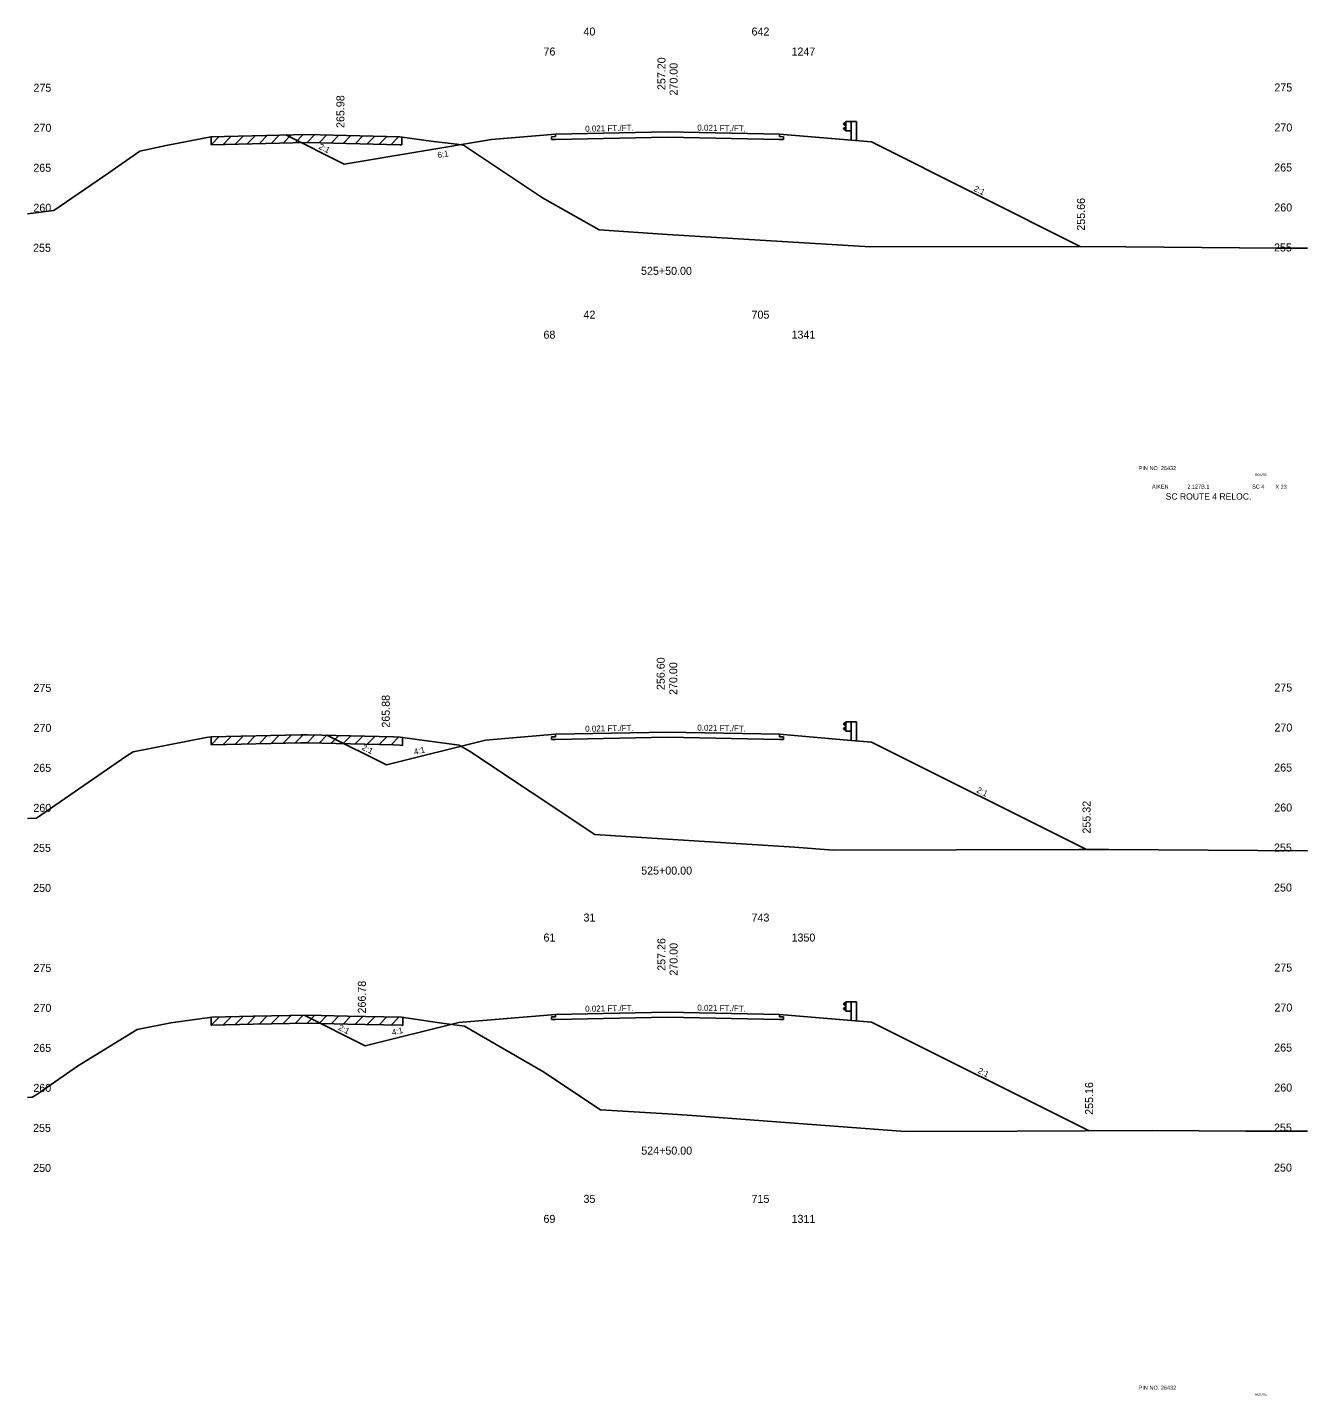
# Model space of a CAD drawing. Extents: x 2967 to 4323, y -3677 to -817.
# Drawn here: x 3188.8 to 3348.8, y -1162.8 to -991.8 of the extents above; entities that cross this region are included whole.
import ezdxf

# ---------------------------------------------------------------- set-up
doc = ezdxf.new("R2010")
doc.units = 0
for name, color, linetype in [('Level 1', 7, 'Continuous'), ('Level 10', 7, 'Continuous'), ('Level 11', 7, 'Continuous'), ('Level 12', 7, 'Continuous'), ('Level 20', 7, 'Continuous'), ('Level 24', 7, 'Continuous'), ('Level 3', 7, 'Continuous'), ('Level 32', 7, 'Continuous'), ('Level 33', 7, 'Continuous'), ('Level 59', 7, 'Continuous'), ('Level 6', 7, 'Continuous'), ('Level 60', 7, 'Continuous'), ('Level 61', 7, 'Continuous'), ('Level 7', 7, 'Continuous')]:
    doc.layers.add(name, color=color, linetype=linetype)

msp = doc.modelspace()

# ---------------------------------------------------------------- linework, layer by layer
at = {"layer": 'Level 11'}
for p, q in [((3254.76, -1005.43), (3254.26, -1005.44)), ((3254.26, -1005.44), (3254.26, -1005.78)), ((3254.76, -1005.13), (3254.76, -1005.43)), ((3282.76, -1005.43), (3282.76, -1005.13)), ((3283.26, -1005.44), (3282.76, -1005.43)), ((3283.26, -1005.78), (3283.26, -1005.44)), ((3254.26, -1005.78), (3254.76, -1005.77)), ((3282.76, -1005.77), (3283.26, -1005.78)), ((3254.76, -1080.43), (3254.26, -1080.44)), ((3254.26, -1080.44), (3254.26, -1080.78)), ((3254.26, -1080.78), (3254.76, -1080.77)), ((3254.76, -1080.13), (3254.76, -1080.43)), ((3282.76, -1080.43), (3282.76, -1080.13)), ((3283.26, -1080.44), (3282.76, -1080.43)), ((3282.76, -1080.77), (3283.26, -1080.78)), ((3283.26, -1080.78), (3283.26, -1080.44)), ((3254.76, -1115.43), (3254.26, -1115.44)), ((3254.26, -1115.44), (3254.26, -1115.78)), ((3254.26, -1115.78), (3254.76, -1115.77)), ((3254.76, -1115.13), (3254.76, -1115.43)), ((3282.76, -1115.43), (3282.76, -1115.13)), ((3283.26, -1115.44), (3282.76, -1115.43)), ((3282.76, -1115.77), (3283.26, -1115.78)), ((3283.26, -1115.78), (3283.26, -1115.44))]:
    msp.add_line(p, q, dxfattribs=at)
at = {"layer": 'Level 12'}
for p, q in [((3268.76, -1005.48), (3254.76, -1005.77)), ((3282.76, -1005.77), (3268.76, -1005.48)), ((3268.76, -1080.48), (3254.76, -1080.77)), ((3282.76, -1080.77), (3268.76, -1080.48)), ((3268.76, -1115.48), (3254.76, -1115.77)), ((3282.76, -1115.77), (3268.76, -1115.48))]:
    msp.add_line(p, q, dxfattribs=at)
at = {"layer": 'Level 24'}
for p, q in [((3291.03, -1003.62), (3290.76, -1003.82)), ((3290.76, -1003.82), (3290.76, -1003.87)), ((3291.03, -1004.72), (3291.03, -1003.55)), ((3291.03, -1003.55), (3291.7, -1003.55)), ((3291.7, -1003.55), (3291.7, -1005.88)), ((3291.7, -1003.55), (3292.36, -1003.55)), ((3292.36, -1003.55), (3292.36, -1005.93)), ((3290.76, -1003.87), (3291.03, -1004.07)), ((3290.76, -1004.39), (3291.03, -1004.19)), ((3290.76, -1004.44), (3290.76, -1004.39)), ((3291.03, -1004.64), (3290.76, -1004.44)), ((3291.03, -1004.72), (3291.7, -1004.72)), ((3291.03, -1078.62), (3290.76, -1078.82)), ((3290.76, -1078.82), (3290.76, -1078.87)), ((3290.76, -1078.87), (3291.03, -1079.07)), ((3291.03, -1079.72), (3291.03, -1078.55)), ((3291.03, -1078.55), (3291.7, -1078.55)), ((3291.7, -1078.55), (3291.7, -1080.88)), ((3291.7, -1078.55), (3292.36, -1078.55)), ((3292.36, -1078.55), (3292.36, -1080.93)), ((3290.76, -1079.39), (3291.03, -1079.19)), ((3290.76, -1079.44), (3290.76, -1079.39)), ((3291.03, -1079.64), (3290.76, -1079.44)), ((3291.03, -1079.72), (3291.7, -1079.72)), ((3291.03, -1113.62), (3290.76, -1113.82)), ((3290.76, -1113.82), (3290.76, -1113.87)), ((3290.76, -1113.87), (3291.03, -1114.07)), ((3290.76, -1114.39), (3291.03, -1114.19)), ((3290.76, -1114.44), (3290.76, -1114.39)), ((3291.03, -1114.64), (3290.76, -1114.44)), ((3291.03, -1114.72), (3291.03, -1113.55)), ((3291.03, -1113.55), (3291.7, -1113.55)), ((3291.03, -1114.72), (3291.7, -1114.72)), ((3291.7, -1113.55), (3291.7, -1115.88)), ((3291.7, -1113.55), (3292.36, -1113.55)), ((3292.36, -1113.55), (3292.36, -1115.93))]:
    msp.add_line(p, q, dxfattribs=at)
at = {"layer": 'Level 59'}
for p, q in [((3254.76, -1005.13), (3268.76, -1004.84)), ((3268.76, -1004.84), (3282.76, -1005.13)), ((3254.76, -1080.13), (3268.76, -1079.84)), ((3268.76, -1079.84), (3282.76, -1080.13)), ((3254.76, -1115.13), (3268.76, -1114.84)), ((3268.76, -1114.84), (3282.76, -1115.13))]:
    msp.add_line(p, q, dxfattribs=at)
at = {"layer": 'Level 6'}
for p, q in [((3246.76, -1005.8), (3254.76, -1005.13)), ((3282.76, -1005.13), (3290.76, -1005.8)), ((3290.76, -1005.8), (3294.26, -1006.09)), ((3246.01, -1080.86), (3254.76, -1080.13)), ((3282.76, -1080.13), (3290.76, -1080.8)), ((3290.76, -1080.8), (3294.26, -1081.09)), ((3246.01, -1080.86), (3233.62, -1083.96)), ((3242.68, -1116.14), (3230.99, -1119.06)), ((3242.68, -1116.14), (3254.76, -1115.13)), ((3282.76, -1115.13), (3290.76, -1115.8)), ((3290.76, -1115.8), (3294.26, -1116.09))]:
    msp.add_line(p, q, dxfattribs=at)
at = {"layer": 'Level 60'}
for p, q in [((3206.12, -1006.54), (3211.69, -1005.44)), ((3211.69, -1005.44), (3218.54, -1005.29)), ((3218.54, -1005.29), (3223.7, -1005.16)), ((3223.7, -1005.16), (3230.3, -1005.32)), ((3230.3, -1005.32), (3235.31, -1005.44)), ((3235.31, -1005.44), (3239.52, -1006.02)), ((3198.95, -1009.94), (3202.8, -1007.24)), ((3202.8, -1007.24), (3206.12, -1006.54)), ((3239.52, -1006.02), (3242.41, -1006.36)), ((3242.41, -1006.36), (3243.25, -1006.48)), ((3243.25, -1006.48), (3253.14, -1013.09)), ((3192.08, -1014.68), (3198.95, -1009.94)), ((3253.14, -1013.09), (3260.21, -1017.08)), ((3188.76, -1015.06), (3192.08, -1014.68)), ((3260.21, -1017.08), (3268.76, -1017.64)), ((3268.76, -1017.64), (3276.91, -1018.18)), ((3276.91, -1018.18), (3294.08, -1019.19)), ((3294.08, -1019.19), (3315.44, -1019.14)), ((3315.44, -1019.14), (3326.04, -1019.22)), ((3326.04, -1019.22), (3344.98, -1019.36)), ((3344.98, -1019.36), (3348.76, -1019.36)), ((3201.98, -1082.33), (3211.09, -1080.53)), ((3211.09, -1080.53), (3211.71, -1080.45)), ((3211.71, -1080.45), (3222.92, -1080.19)), ((3222.92, -1080.19), (3223.75, -1080.18)), ((3223.75, -1080.18), (3234.5, -1080.45)), ((3234.5, -1080.45), (3235.34, -1080.47)), ((3235.34, -1080.47), (3235.92, -1080.55)), ((3235.92, -1080.55), (3242.72, -1081.49)), ((3201.08, -1082.89), (3201.98, -1082.33)), ((3242.72, -1081.49), (3244.01, -1082.24)), ((3244.01, -1082.24), (3259.69, -1092.66)), ((3189.91, -1090.61), (3201.08, -1082.89)), ((3188.76, -1090.66), (3189.91, -1090.61)), ((3259.69, -1092.66), (3268.76, -1093.24)), ((3268.76, -1093.24), (3284.62, -1094.24)), ((3284.62, -1094.24), (3289.48, -1094.61)), ((3289.48, -1094.61), (3320.21, -1094.53)), ((3320.21, -1094.53), (3323.9, -1094.51)), ((3323.9, -1094.51), (3348.76, -1094.68)), ((3202.5, -1117.02), (3206.68, -1116.19)), ((3206.68, -1116.19), (3211.82, -1115.48)), ((3211.82, -1115.48), (3216.97, -1115.36)), ((3216.97, -1115.36), (3223.79, -1115.23)), ((3223.79, -1115.23), (3228.75, -1115.35)), ((3228.75, -1115.35), (3235.52, -1115.5)), ((3235.52, -1115.5), (3240.27, -1116.19)), ((3240.27, -1116.19), (3243.4, -1116.62)), ((3243.4, -1116.62), (3253.19, -1122.26)), ((3195.03, -1121.62), (3202.5, -1117.02)), ((3189.93, -1125.14), (3195.03, -1121.62)), ((3253.19, -1122.26), (3260.38, -1127.05)), ((3189.36, -1125.49), (3189.93, -1125.14)), ((3188.76, -1125.51), (3189.36, -1125.49)), ((3260.38, -1127.05), (3268.76, -1127.58)), ((3268.76, -1127.58), (3271.84, -1127.78)), ((3271.84, -1127.78), (3298.48, -1129.79)), ((3298.48, -1129.79), (3312.44, -1129.75)), ((3312.44, -1129.75), (3329.43, -1129.63)), ((3329.43, -1129.63), (3340.98, -1129.71)), ((3340.98, -1129.71), (3348.76, -1129.71))]:
    msp.add_line(p, q, dxfattribs=at)
at = {"layer": 'Level 61'}
for p, q in [((3212.74, -1005.42), (3211.72, -1006.44)), ((3211.72, -1005.44), (3211.72, -1006.44)), ((3214.24, -1005.38), (3213.22, -1006.41)), ((3215.74, -1005.35), (3214.72, -1006.37)), ((3217.24, -1005.32), (3216.22, -1006.34)), ((3218.74, -1005.28), (3217.72, -1006.31)), ((3220.24, -1005.25), (3219.22, -1006.27)), ((3221.74, -1005.21), (3220.72, -1006.23)), ((3223.24, -1005.17), (3222.22, -1006.2)), ((3224.69, -1005.18), (3223.72, -1006.16)), ((3226.19, -1005.22), (3225.22, -1006.2)), ((3227.69, -1005.26), (3226.72, -1006.23)), ((3229.19, -1005.3), (3228.22, -1006.27)), ((3230.69, -1005.33), (3229.72, -1006.31)), ((3232.2, -1005.37), (3231.22, -1006.34)), ((3233.7, -1005.4), (3232.72, -1006.38)), ((3235.2, -1005.43), (3234.22, -1006.41)), ((3235.57, -1006.47), (3235.57, -1005.47)), ((3211.72, -1006.44), (3218.54, -1006.29)), ((3218.54, -1006.29), (3223.7, -1006.16)), ((3223.7, -1006.16), (3230.3, -1006.32)), ((3230.3, -1006.32), (3235.31, -1006.44)), ((3235.31, -1006.44), (3235.57, -1006.47)), ((3212.74, -1080.42), (3211.71, -1081.45)), ((3211.71, -1080.45), (3211.71, -1081.45)), ((3214.24, -1080.39), (3213.21, -1081.41)), ((3215.74, -1080.36), (3214.71, -1081.38)), ((3217.24, -1080.32), (3216.21, -1081.35)), ((3218.74, -1080.29), (3217.71, -1081.31)), ((3220.24, -1080.25), (3219.21, -1081.28)), ((3221.74, -1080.22), (3220.71, -1081.24)), ((3223.23, -1080.19), (3222.21, -1081.21)), ((3224.69, -1080.2), (3223.71, -1081.18)), ((3226.19, -1080.24), (3225.21, -1081.22)), ((3227.69, -1080.28), (3226.71, -1081.25)), ((3229.19, -1080.32), (3228.21, -1081.29)), ((3230.69, -1080.35), (3229.71, -1081.33)), ((3232.19, -1080.39), (3231.21, -1081.37)), ((3233.69, -1080.43), (3232.71, -1081.4)), ((3235.19, -1080.46), (3234.21, -1081.44)), ((3235.64, -1081.51), (3235.64, -1080.51)), ((3211.71, -1081.45), (3222.92, -1081.19)), ((3222.92, -1081.19), (3223.75, -1081.18)), ((3223.75, -1081.18), (3234.5, -1081.45)), ((3234.5, -1081.45), (3235.34, -1081.47)), ((3235.34, -1081.47), (3235.64, -1081.51)), ((3212.75, -1115.46), (3211.71, -1116.49)), ((3211.71, -1115.49), (3211.71, -1116.49)), ((3211.71, -1116.49), (3211.82, -1116.48)), ((3211.82, -1116.48), (3216.97, -1116.36)), ((3214.23, -1115.42), (3213.21, -1116.45)), ((3215.73, -1115.39), (3214.71, -1116.41)), ((3217.23, -1115.36), (3216.21, -1116.38)), ((3216.97, -1116.36), (3223.79, -1116.23)), ((3218.73, -1115.33), (3217.71, -1116.35)), ((3220.23, -1115.3), (3219.21, -1116.32)), ((3221.73, -1115.27), (3220.71, -1116.29)), ((3223.23, -1115.24), (3222.21, -1116.26)), ((3224.69, -1115.25), (3223.71, -1116.23)), ((3223.79, -1116.23), (3228.75, -1116.35)), ((3226.18, -1115.29), (3225.21, -1116.26)), ((3227.68, -1115.33), (3226.71, -1116.3)), ((3229.19, -1115.36), (3228.21, -1116.34)), ((3228.75, -1116.35), (3235.52, -1116.5)), ((3230.69, -1115.4), (3229.71, -1116.37)), ((3232.19, -1115.43), (3231.21, -1116.41)), ((3233.69, -1115.46), (3232.71, -1116.44)), ((3235.19, -1115.49), (3234.21, -1116.47)), ((3235.52, -1116.5), (3235.7, -1116.53)), ((3235.7, -1116.53), (3235.7, -1115.53))]:
    msp.add_line(p, q, dxfattribs=at)
at = {"layer": 'Level 7'}
for p, q in [((3221.08, -1005.22), (3228.36, -1008.87)), ((3228.36, -1008.87), (3246.76, -1005.8)), ((3294.26, -1006.09), (3320.43, -1019.18)), ((3226.18, -1080.24), (3233.62, -1083.96)), ((3294.26, -1081.09), (3321.13, -1094.53)), ((3223.34, -1115.24), (3230.99, -1119.06)), ((3294.26, -1116.09), (3321.45, -1129.69))]:
    msp.add_line(p, q, dxfattribs=at)

# ---------------------------------------------------------------- texts
at = {"layer": 'Level 1'}
for s, p in [('40', (3258.26, -992.79)), ('642', (3279.26, -992.79)), ('76', (3253.26, -995.29)), ('1247', (3284.26, -995.29)), ('42', (3258.26, -1028.18)), ('705', (3279.26, -1028.18)), ('68', (3253.26, -1030.68)), ('1341', (3284.26, -1030.68)), ('31', (3258.26, -1103.53)), ('743', (3279.26, -1103.53)), ('61', (3253.26, -1106.03)), ('1350', (3284.26, -1106.03)), ('35', (3258.26, -1138.69)), ('715', (3279.26, -1138.69)), ('69', (3253.26, -1141.19)), ('1311', (3284.26, -1141.19))]:
    msp.add_text(s, height=1, dxfattribs=at).set_placement(p)
at = {"layer": 'Level 10'}
for s, p in [('257.20', (3268.5, -999.61)), ('256.60', (3268.41, -1074.6)), ('257.26', (3268.5, -1109.69))]:
    msp.add_text(s, height=1, rotation=90, dxfattribs=at).set_placement(p)
for s, p in [('525+50.00', (3265.45, -1022.7)), ('525+00.00', (3265.47, -1097.66)), ('524+50.00', (3265.48, -1132.66))]:
    msp.add_text(s, height=1, dxfattribs=at).set_placement(p)
at = {"layer": 'Level 20'}
for s, height, p in [('PIN NO. 26432', 0.5, (3327.65, -1047.11)), ('ROUTE', 0.3, (3342.19, -1047.85)), ('AIKEN', 0.5, (3329.31, -1049.41)), ('SC ROUTE 4 RELOC.', 0.8, (3331.02, -1050.8)), (' 2.127B.1', 0.5, (3333.53, -1049.41)), ('SC 4', 0.5, (3341.82, -1049.41)), ('X 23', 0.5, (3344.73, -1049.44)), ('PIN NO. 26432', 0.5, (3327.65, -1162.04)), ('ROUTE', 0.3, (3342.19, -1162.78))]:
    msp.add_text(s, height=height, dxfattribs=at).set_placement(p)
at = {"layer": 'Level 3'}
for s, p in [(' 275', (3189.15, -999.82)), (' 275', (3344.23, -999.78)), (' 270', (3189.16, -1004.82)), (' 270', (3344.24, -1004.78)), (' 265', (3189.13, -1009.82)), (' 265', (3344.21, -1009.78)), (' 260', (3189.14, -1014.82)), (' 260', (3344.22, -1014.78)), (' 255', (3189.1, -1019.82)), (' 255', (3344.18, -1019.78)), (' 275', (3189.15, -1074.82)), (' 275', (3344.23, -1074.78)), (' 270', (3189.16, -1079.82)), (' 270', (3344.24, -1079.78)), (' 265', (3189.13, -1084.82)), (' 265', (3344.21, -1084.78)), (' 260', (3189.14, -1089.82)), (' 260', (3344.22, -1089.78)), (' 255', (3189.1, -1094.82)), (' 255', (3344.18, -1094.78)), (' 250', (3189.11, -1099.82)), (' 250', (3344.19, -1099.78)), (' 275', (3189.15, -1109.82)), (' 275', (3344.23, -1109.78)), (' 270', (3189.16, -1114.82)), (' 270', (3344.24, -1114.78)), (' 265', (3189.13, -1119.82)), (' 265', (3344.21, -1119.78)), (' 260', (3189.14, -1124.82)), (' 260', (3344.22, -1124.78)), (' 255', (3189.1, -1129.82)), (' 255', (3344.18, -1129.78)), (' 250', (3189.11, -1134.82)), (' 250', (3344.19, -1134.78))]:
    msp.add_text(s, height=1, dxfattribs=at).set_placement(p)
at = {"layer": 'Level 32'}
for s, rotation, p in [('0.021 FT./FT.', 1.1916, (3258.47, -1004.81)), ('0.021 FT./FT.', 358.8084, (3272.48, -1004.67)), ('2:1', 333.435, (3225.09, -1006.91)), ('6:1', 9.4623, (3240.07, -1008.12)), ('2:1', 333.435, (3306.95, -1012.16)), ('0.021 FT./FT.', 1.1916, (3258.47, -1079.81)), ('0.021 FT./FT.', 358.8084, (3272.48, -1079.67)), ('2:1', 333.435, (3230.49, -1082)), ('4:1', 14.0362, (3237.16, -1082.71)), ('2:1', 333.435, (3307.3, -1087.33)), ('0.021 FT./FT.', 1.1916, (3258.47, -1114.81)), ('0.021 FT./FT.', 358.8084, (3272.48, -1114.67)), ('2:1', 333.435, (3227.55, -1117.02)), ('4:1', 14.0362, (3234.4, -1117.78)), ('2:1', 333.435, (3307.46, -1122.41))]:
    msp.add_text(s, height=0.75, rotation=rotation, dxfattribs=at).set_placement(p)
at = {"layer": 'Level 33'}
for s, p in [('265.98', (3228.38, -1004.35)), ('255.66', (3320.93, -1017.18)), ('265.88', (3234.05, -1079.3)), ('255.32', (3321.63, -1092.53)), ('266.78', (3231.06, -1115.02)), ('255.16', (3321.95, -1127.69))]:
    msp.add_text(s, height=1, rotation=90, dxfattribs=at).set_placement(p)
at = {"layer": 'Level 59'}
for p in [(3270.02, -1000.66), (3269.98, -1075.58), (3270.02, -1110.66)]:
    msp.add_text(' 270.00', height=1, rotation=90, dxfattribs=at).set_placement(p)

doc.saveas('drawing.dxf')
